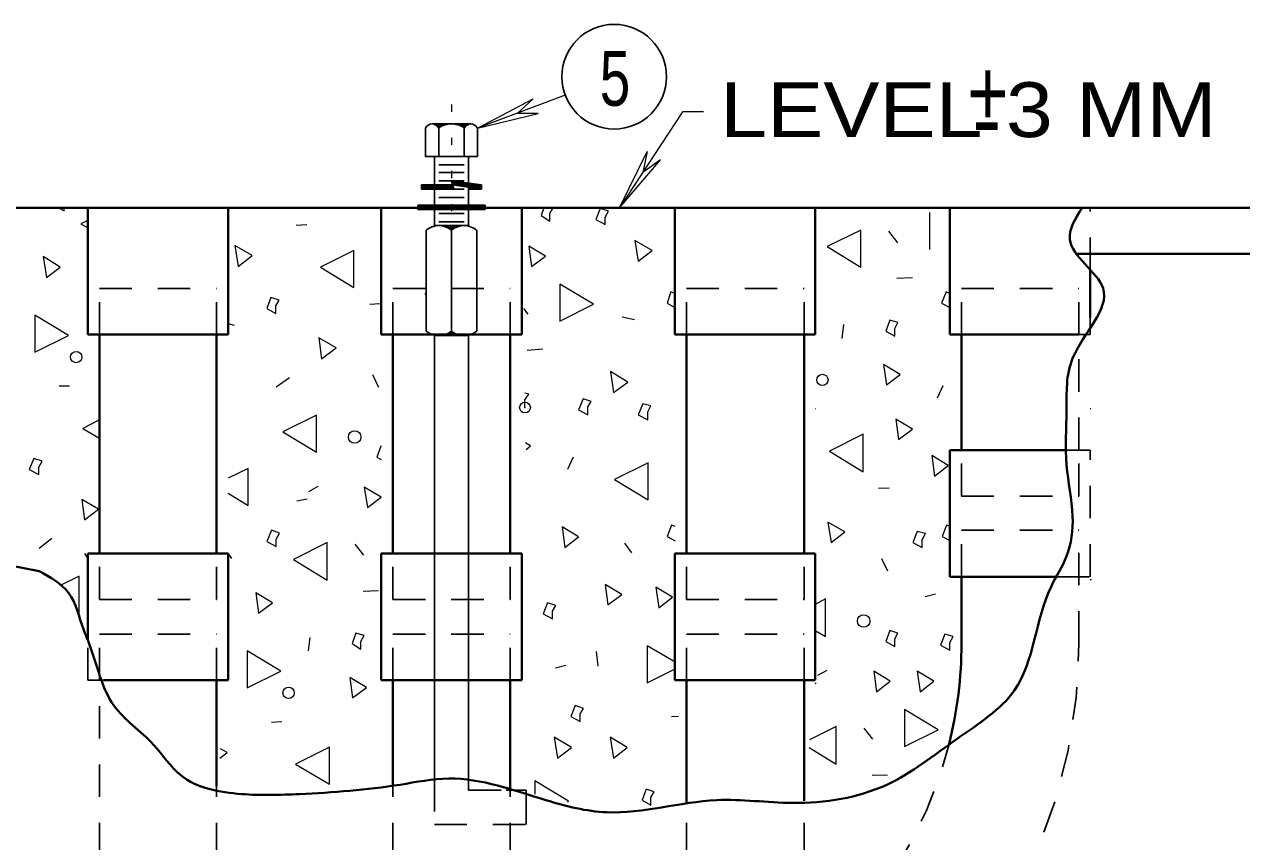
# Model space of a CAD drawing. Extents: x 312583 to 312854, y 144419 to 144597.
# Drawn here: x 312756.71 to 312773.6, y 144448.42 to 144459.75 of the extents above; entities that cross this region are included whole.
import ezdxf
from ezdxf.enums import TextEntityAlignment as Align

# ---------------------------------------------------------------- set-up
doc = ezdxf.new("R2010")
doc.units = 0
doc.header["$LTSCALE"] = 0.3
doc.header["$PDMODE"] = 32
doc.header["$PDSIZE"] = 0.15
doc.linetypes.add('DOTTED', pattern=[1.5, 0.3, -1.2])
doc.linetypes.add('SHORT_DASHED', pattern=[2.7, 1.5, -1.2])
for name, color, linetype, lineweight in [('1', 7, 'Continuous', 25), ('2', 7, 'Continuous', 13), ('52', 7, 'Continuous', 25)]:
    doc.layers.add(name, color=color, linetype=linetype, lineweight=lineweight)

msp = doc.modelspace()

# ---------------------------------------------------------------- linework, layer by layer
at = {"layer": '1', "lineweight": 40}
for p, q in [((312734.5276, 144457.2014), (312777.9746, 144457.2014)), ((312757.5966, 144455.4457), (312757.5966, 144457.2014)), ((312759.544, 144455.4457), (312759.544, 144457.2014)), ((312761.6676, 144455.4457), (312761.6676, 144457.2014)), ((312763.615, 144455.4457), (312763.615, 144457.2014)), ((312765.7386, 144455.4457), (312765.7386, 144457.2014)), ((312767.686, 144455.4457), (312767.686, 144457.2014)), ((312769.5566, 144455.4457), (312769.5566, 144457.2014)), ((312771.3123, 144456.565), (312784.1233, 144456.565)), ((312771.504, 144455.6834), (312771.504, 144456.3427)), ((312757.5966, 144455.4457), (312759.544, 144455.4457)), ((312757.7576, 144452.4097), (312757.7576, 144455.4457)), ((312759.383, 144452.4097), (312759.383, 144455.4457)), ((312761.6676, 144455.4457), (312763.615, 144455.4457)), ((312761.8286, 144452.4097), (312761.8286, 144455.4457)), ((312763.454, 144452.4097), (312763.454, 144455.4457)), ((312765.7386, 144455.4457), (312767.686, 144455.4457)), ((312765.8996, 144452.4097), (312765.8996, 144455.4457)), ((312767.5326, 144452.4097), (312767.5326, 144455.4457)), ((312769.5566, 144455.4457), (312771.343, 144455.4457)), ((312769.7176, 144453.8434), (312769.7176, 144455.4457)), ((312769.5566, 144452.0877), (312769.5566, 144453.8434)), ((312769.5566, 144453.8434), (312771.1743, 144453.8434)), ((312757.5966, 144452.4097), (312759.544, 144452.4097)), ((312757.5966, 144451.2137), (312757.5966, 144452.4097)), ((312759.544, 144450.654), (312759.544, 144452.4097)), ((312761.6676, 144450.654), (312761.6676, 144452.4097)), ((312761.6676, 144452.4097), (312763.615, 144452.4097)), ((312763.615, 144450.654), (312763.615, 144452.4097)), ((312765.7386, 144450.654), (312765.7386, 144452.4097)), ((312765.7386, 144452.4097), (312767.686, 144452.4097)), ((312767.686, 144450.654), (312767.686, 144452.4097)), ((312769.5566, 144452.0877), (312771.0363, 144452.0877)), ((312769.7176, 144451.16), (312769.7176, 144452.0877)), ((312757.819, 144450.654), (312759.544, 144450.654)), ((312759.383, 144449.182), (312759.383, 144450.654)), ((312761.6676, 144450.654), (312763.615, 144450.654)), ((312761.8286, 144449.1974), (312761.8286, 144450.654)), ((312763.454, 144449.113), (312763.454, 144450.654)), ((312765.7386, 144450.654), (312767.686, 144450.654)), ((312765.8996, 144448.9444), (312765.8996, 144450.654)), ((312767.5326, 144448.9827), (312767.5326, 144450.654))]:
    msp.add_line(p, q, dxfattribs=at)
at = {"layer": '1', "linetype": 'SHORT_DASHED'}
for p, q in [((312771.504, 144456.3427), (312771.504, 144457.2014)), ((312757.7576, 144456.082), (312759.383, 144456.082)), ((312757.7576, 144455.4457), (312757.7576, 144456.082)), ((312759.383, 144455.4457), (312759.383, 144456.082)), ((312761.8286, 144455.4457), (312761.8286, 144456.082)), ((312761.8286, 144456.082), (312763.454, 144456.082)), ((312763.454, 144455.4457), (312763.454, 144456.082)), ((312765.8996, 144456.082), (312767.5326, 144456.082)), ((312765.8996, 144455.4457), (312765.8996, 144456.082)), ((312767.5326, 144455.4457), (312767.5326, 144456.082)), ((312769.7176, 144456.082), (312771.343, 144456.082)), ((312769.7176, 144455.4457), (312769.7176, 144456.082)), ((312771.343, 144455.4457), (312771.343, 144456.082)), ((312771.504, 144455.4457), (312771.504, 144455.6834)), ((312771.343, 144453.8434), (312771.343, 144455.4457)), ((312771.343, 144455.4457), (312771.504, 144455.4457)), ((312769.7176, 144453.207), (312769.7176, 144453.8434)), ((312771.1743, 144453.8434), (312771.504, 144453.8434)), ((312771.343, 144453.207), (312771.343, 144453.8434)), ((312771.504, 144452.0877), (312771.504, 144453.8434)), ((312769.7176, 144453.207), (312771.343, 144453.207)), ((312769.7176, 144452.7317), (312771.343, 144452.7317)), ((312769.7176, 144452.0877), (312769.7176, 144452.7317)), ((312771.343, 144451.16), (312771.343, 144452.7317)), ((312757.7576, 144451.7734), (312757.7576, 144452.4097)), ((312759.383, 144451.7734), (312759.383, 144452.4097)), ((312761.8286, 144451.7734), (312761.8286, 144452.4097)), ((312763.454, 144451.7734), (312763.454, 144452.4097)), ((312765.8996, 144451.7734), (312765.8996, 144452.4097)), ((312767.5326, 144451.7734), (312767.5326, 144452.4097)), ((312771.0363, 144452.0877), (312771.504, 144452.0877)), ((312757.7576, 144451.7734), (312759.383, 144451.7734)), ((312761.8286, 144451.7734), (312763.454, 144451.7734)), ((312765.8996, 144451.7734), (312767.5326, 144451.7734)), ((312757.5966, 144450.654), (312757.5966, 144451.2137)), ((312757.7576, 144451.2904), (312759.383, 144451.2904)), ((312757.7576, 144450.654), (312757.7576, 144451.2904)), ((312759.383, 144450.654), (312759.383, 144451.2904)), ((312761.8286, 144450.654), (312761.8286, 144451.2904)), ((312761.8286, 144451.2904), (312763.454, 144451.2904)), ((312763.454, 144450.654), (312763.454, 144451.2904)), ((312765.8996, 144451.2904), (312767.5326, 144451.2904)), ((312765.8996, 144450.654), (312765.8996, 144451.2904)), ((312767.5326, 144450.654), (312767.5326, 144451.2904)), ((312757.5966, 144450.654), (312757.819, 144450.654)), ((312757.7576, 144439.315), (312757.7576, 144450.654)), ((312759.383, 144439.315), (312759.383, 144449.182)), ((312761.8286, 144439.315), (312761.8286, 144449.1974)), ((312763.454, 144439.315), (312763.454, 144449.113)), ((312767.5326, 144439.315), (312767.5326, 144448.9827)), ((312765.8996, 144439.315), (312765.8996, 144448.9444))]:
    msp.add_line(p, q, dxfattribs=at)
at = {"layer": '1', "lineweight": 13}
msp.add_line((312762.994, 144456.2584), (312763.0016, 144456.2507), dxfattribs=at)
at = {"layer": '1', "linetype": 'SHORT_DASHED'}
for radius, end in [(7.3792, 0), (5.75, 345.9494)]:
    msp.add_arc((312763.967, 144451.1639), radius, 270, end, dxfattribs=at)
at = {"layer": '1', "lineweight": 40}
msp.add_arc((312763.967, 144451.1639), 5.75, 345.9494, 0, dxfattribs=at)
for points in [[(312756.922, 144452.1644), (312757.3283, 144451.8654), (312757.5353, 144451.3594), (312757.6196, 144451.1447), (312757.957, 144450.3014), (312758.509, 144449.757), (312758.8846, 144449.3354), (312759.728, 144449.0747), (312760.533, 144449.0747), (312761.9283, 144449.205), (312762.603, 144449.2894), (312763.9523, 144448.9904), (312764.7956, 144448.8217), (312766.3213, 144448.9904), (312767.3716, 144448.952), (312768.6826, 144449.205), (312769.6563, 144449.8414), (312770.4536, 144450.516), (312770.9596, 144451.9497), (312771.1743, 144452.3714), (312771.2586, 144452.9234), (312771.1743, 144453.6364), (312771.1743, 144454.3954), (312771.2586, 144455.116), (312771.6803, 144456.0897), (312771.2203, 144456.7644), (312771.389, 144457.2014)], [(312756.922, 144452.1644), (312755.818, 144452.471), (312755.3273, 144452.724), (312753.8783, 144453.092), (312753.1806, 144453.4217), (312751.3023, 144453.8894)]]:
    msp.add_spline(points, degree=3, dxfattribs=at)
at = {"layer": '2'}
for p, q in [((312764.972, 144457.2014), (312765.3553, 144457.9834)), ((312765.3553, 144457.9834), (312765.294, 144457.692)), ((312764.972, 144457.2014), (312765.5393, 144457.8684)), ((312765.5393, 144457.8684), (312765.294, 144457.692)), ((312764.006, 144457.1247), (312764.052, 144457.2014)), ((312769.273, 144457.14), (312769.273, 144456.6264)), ((312760.487, 144456.9637), (312760.6326, 144456.9714)), ((312768.7056, 144456.8794), (312768.8283, 144456.7184)), ((312768.8206, 144456.2277), (312769.0353, 144456.2354)), ((312761.5066, 144455.8674), (312761.6523, 144455.875)), ((312763.638, 144455.806), (312763.6993, 144455.7294)), ((312759.544, 144455.599), (312759.6283, 144455.576)), ((312765.0103, 144455.691), (312765.179, 144455.6527)), ((312768.0616, 144455.392), (312768.0846, 144455.5837)), ((312763.6916, 144455.231), (312763.9063, 144455.2464)), ((312761.545, 144454.8937), (312761.6293, 144454.7174)), ((312757.198, 144454.7327), (312757.3436, 144454.7327)), ((312760.395, 144454.8477), (312760.211, 144454.7174)), ((312769.457, 144454.7327), (312769.3803, 144454.564)), ((312763.661, 144454.4337), (312763.661, 144454.541)), ((312767.686, 144454.4184), (312767.6936, 144454.4184)), ((312771.504, 144454.4184), (312771.5116, 144454.4184)), ((312764.328, 144453.7437), (312764.2513, 144453.575)), ((312759.544, 144453.2454), (312759.82, 144453.0767)), ((312760.6633, 144453.2684), (312760.7936, 144453.345)), ((312768.5676, 144453.3144), (312768.7133, 144453.322)), ((312760.4946, 144453.138), (312760.6403, 144453.1687)), ((312757.0983, 144452.6167), (312756.922, 144452.4787)), ((312761.2996, 144452.54), (312761.4223, 144452.3867)), ((312765.041, 144452.5554), (312765.1406, 144452.4174)), ((312757.5506, 144452.4097), (312757.5966, 144452.3407)), ((312759.544, 144452.4097), (312759.59, 144452.3407)), ((312768.606, 144452.3407), (312768.6903, 144452.172)), ((312771.504, 144452.0494), (312771.5193, 144452.0494)), ((312761.4146, 144451.8884), (312761.6293, 144451.896)), ((312769.2116, 144451.8117), (312769.3573, 144451.85)), ((312767.686, 144451.344), (312767.8316, 144451.2597)), ((312760.6556, 144451.0604), (312760.6786, 144451.2444)), ((312764.65, 144451.0527), (312764.673, 144450.8457)), ((312765.754, 144450.8994), (312765.3553, 144451.1294)), ((312764.0826, 144450.8227), (312764.2283, 144450.861)), ((312767.7243, 144450.723), (312767.8546, 144450.792)), ((312767.686, 144450.608), (312767.7013, 144450.6157)), ((312765.6926, 144450.148), (312765.7923, 144450.1557)), ((312760.142, 144450.0714), (312760.2876, 144450.079)), ((312768.3606, 144449.987), (312768.4833, 144449.8337)), ((312767.6016, 144449.7187), (312767.9773, 144449.4887)), ((312768.4756, 144449.3354), (312768.6903, 144449.343)), ((312763.799, 144449.2587), (312763.799, 144449.0747))]:
    msp.add_line(p, q, dxfattribs=at)
for points in [[(312766.1373, 144458.5354), (312765.846, 144458.5354), (312764.972, 144457.2014)], [(312757.1903, 144457.2014), (312757.267, 144457.163), (312757.267, 144457.2014)], [(312763.9216, 144457.2014), (312763.8833, 144457.094), (312764.006, 144457.0174), (312764.006, 144457.1247)], [(312757.5966, 144457.025), (312757.497, 144456.979), (312757.5966, 144456.9254)], [(312765.7386, 144456.013), (312765.685, 144456.036), (312765.6313, 144455.8827), (312765.7386, 144455.8214)], [(312769.5566, 144456.013), (312769.503, 144456.036), (312769.4416, 144455.8827), (312769.5566, 144455.8214)], [(312763.661, 144454.541), (312763.7146, 144454.6177), (312763.661, 144454.633)], [(312757.75, 144454.2574), (312757.5276, 144454.1424), (312757.75, 144454.012)], [(312761.6676, 144453.897), (312761.66, 144453.897), (312761.6063, 144453.7437), (312761.6676, 144453.713)], [(312763.6763, 144453.851), (312763.7376, 144453.9047), (312763.6686, 144453.943)], [(312759.82, 144453.0767), (312759.82, 144453.5904), (312759.544, 144453.4524)], [(312765.7463, 144452.7854), (312765.6926, 144452.8007), (312765.6313, 144452.6474), (312765.7463, 144452.586)], [(312769.5643, 144452.7854), (312769.5106, 144452.8007), (312769.4493, 144452.6474), (312769.5643, 144452.586)], [(312757.474, 144451.5817), (312757.474, 144452.0954), (312757.2133, 144451.965)], [(312767.8316, 144451.2597), (312767.8316, 144451.781), (312767.686, 144451.7044)], [(312765.3553, 144451.1294), (312765.3553, 144450.6157), (312765.754, 144450.815)], [(312767.9773, 144449.4887), (312767.9773, 144450.01), (312767.6093, 144449.826)], [(312759.429, 144449.573), (312759.5286, 144449.6497), (312759.4366, 144449.7034)], [(312764.2513, 144448.9674), (312764.2666, 144448.975), (312763.799, 144449.2587)]]:
    msp.add_lwpolyline(points, dxfattribs=at)
for points in [[(312764.7726, 144457.071), (312764.8186, 144457.1554), (312764.7036, 144457.1937), (312764.6423, 144457.0404), (312764.7726, 144456.9714)], [(312765.2326, 144456.4654), (312765.4243, 144456.611), (312765.1866, 144456.749)], [(312768.3223, 144456.381), (312768.3223, 144456.8947), (312767.8546, 144456.6647)], [(312759.682, 144456.3887), (312759.8736, 144456.542), (312759.636, 144456.68)], [(312761.2843, 144456.0974), (312761.2843, 144456.611), (312760.8243, 144456.381)], [(312763.753, 144456.3887), (312763.9446, 144456.5344), (312763.7146, 144456.6724)], [(312757.0216, 144456.2354), (312757.2133, 144456.381), (312756.9756, 144456.5267)], [(312764.144, 144456.1434), (312764.144, 144455.6297), (312764.6116, 144455.8674)], [(312760.2033, 144455.8444), (312760.2493, 144455.921), (312760.1343, 144455.9594), (312760.0806, 144455.806), (312760.2033, 144455.737)], [(312756.8606, 144455.714), (312756.8606, 144455.2004), (312757.3283, 144455.4304)], [(312768.79, 144455.53), (312768.836, 144455.6144), (312768.721, 144455.645), (312768.6673, 144455.4917), (312768.79, 144455.4227)], [(312760.8396, 144455.1084), (312761.039, 144455.2617), (312760.8013, 144455.3997)], [(312764.8876, 144454.6407), (312765.087, 144454.7864), (312764.8493, 144454.932)], [(312768.675, 144454.748), (312768.8666, 144454.8937), (312768.6366, 144455.0317)], [(312764.535, 144454.4414), (312764.581, 144454.518), (312764.466, 144454.5564), (312764.4046, 144454.403), (312764.535, 144454.334)], [(312765.363, 144454.3724), (312765.409, 144454.4567), (312765.294, 144454.4874), (312765.2326, 144454.334), (312765.363, 144454.265)], [(312760.7706, 144453.8127), (312760.7706, 144454.3264), (312760.303, 144454.0964)], [(312768.8436, 144453.989), (312769.0353, 144454.1347), (312768.8053, 144454.2727)], [(312768.353, 144453.5444), (312768.353, 144454.0657), (312767.8853, 144453.828)], [(312756.9143, 144453.6057), (312756.9603, 144453.69), (312756.8453, 144453.7284), (312756.784, 144453.575), (312756.9143, 144453.506)], [(312769.342, 144453.483), (312769.5336, 144453.6287), (312769.3036, 144453.7667)], [(312765.3706, 144453.1534), (312765.3706, 144453.667), (312764.903, 144453.437)], [(312761.476, 144453.046), (312761.6676, 144453.1917), (312761.43, 144453.3297)], [(312757.5506, 144452.8774), (312757.7423, 144453.023), (312757.5123, 144453.161)], [(312767.9083, 144452.563), (312768.1, 144452.7087), (312767.8623, 144452.8467)], [(312760.211, 144452.609), (312760.257, 144452.6934), (312760.142, 144452.7317), (312760.0806, 144452.5784), (312760.211, 144452.5094)], [(312764.213, 144452.494), (312764.4046, 144452.6397), (312764.1746, 144452.7777)], [(312769.1733, 144452.6014), (312769.2193, 144452.6857), (312769.1043, 144452.7164), (312769.043, 144452.563), (312769.1733, 144452.494)], [(312760.9163, 144452.0417), (312760.9163, 144452.563), (312760.4486, 144452.3254)], [(312759.9656, 144451.5817), (312760.1573, 144451.7274), (312759.9273, 144451.8654)], [(312764.811, 144451.6967), (312765.0026, 144451.8424), (312764.7726, 144451.9804)], [(312765.5163, 144451.6584), (312765.708, 144451.804), (312765.478, 144451.942)], [(312764.0443, 144451.6124), (312764.0903, 144451.689), (312763.9753, 144451.7274), (312763.914, 144451.574), (312764.0443, 144451.505)], [(312768.79, 144451.229), (312768.836, 144451.3057), (312768.721, 144451.344), (312768.6673, 144451.1907), (312768.79, 144451.1217)], [(312761.384, 144451.1907), (312761.43, 144451.275), (312761.315, 144451.3057), (312761.2613, 144451.16), (312761.384, 144451.0834)], [(312769.5566, 144451.1754), (312769.6026, 144451.2597), (312769.4876, 144451.2904), (312769.4263, 144451.137), (312769.5566, 144451.068)], [(312759.8046, 144451.0604), (312759.8046, 144450.5467), (312760.2723, 144450.7767)], [(312761.269, 144450.4087), (312761.4606, 144450.5544), (312761.2306, 144450.6924)], [(312768.537, 144450.493), (312768.7286, 144450.6387), (312768.4986, 144450.7767)], [(312769.1426, 144450.493), (312769.3343, 144450.6387), (312769.1043, 144450.7767)], [(312764.4276, 144450.1864), (312764.4736, 144450.263), (312764.3586, 144450.3014), (312764.2973, 144450.148), (312764.4276, 144450.079)], [(312768.928, 144450.2477), (312768.928, 144449.734), (312769.3956, 144449.964)], [(312764.1133, 144449.573), (312764.305, 144449.7187), (312764.0673, 144449.8644)], [(312764.8876, 144449.573), (312765.0793, 144449.7187), (312764.8416, 144449.8644)], [(312760.947, 144449.2127), (312760.947, 144449.7264), (312760.4793, 144449.4887)], [(312765.409, 144449.0287), (312765.455, 144449.1054), (312765.34, 144449.1437), (312765.2863, 144448.9904), (312765.409, 144448.9214)]]:
    msp.add_lwpolyline(points, close=True, dxfattribs=at)
for centre, radius in [((312757.4345, 144455.1336), 0.0784), ((312767.7875, 144454.8162), 0.0784), ((312761.2989, 144454.0251), 0.0865), ((312768.3603, 144451.4732), 0.0865), ((312760.3814, 144450.4783), 0.0784)]:
    msp.add_circle(centre, radius, dxfattribs=at)
msp.add_point((312763.661, 144454.4337), dxfattribs=at)
at = {"layer": '52', "lineweight": 13}
for p, q in [((312764.2206, 144458.7654), (312763.0016, 144458.3054)), ((312763.0016, 144458.3054), (312763.776, 144458.7117)), ((312763.776, 144458.7117), (312763.5536, 144458.5124)), ((312763.0016, 144458.3054), (312763.845, 144458.5124)), ((312763.845, 144458.5124), (312763.5536, 144458.5124))]:
    msp.add_line(p, q, dxfattribs=at)
at = {"layer": '52', "linetype": 'DOTTED', "lineweight": 13}
msp.add_line((312762.6413, 144458.635), (312762.6413, 144456.956), dxfattribs=at)
at = {"layer": '52'}
for p, q in [((312762.281, 144458.3054), (312762.281, 144457.9144)), ((312762.9096, 144458.3667), (312762.373, 144458.3667)), ((312762.465, 144458.3054), (312762.465, 144457.9144)), ((312762.8176, 144458.3054), (312762.8176, 144457.9144)), ((312763.0016, 144458.3054), (312763.0016, 144457.9144)), ((312763.0016, 144457.9144), (312762.281, 144457.9144)), ((312762.4036, 144457.9144), (312762.4036, 144456.956)), ((312762.879, 144457.9144), (312762.879, 144456.956)), ((312762.8176, 144457.7994), (312762.465, 144457.7994)), ((312762.8176, 144457.692), (312762.465, 144457.692)), ((312762.8176, 144457.577), (312762.465, 144457.577)), ((312762.2273, 144457.5234), (312762.2273, 144457.462)), ((312762.6566, 144457.5234), (312762.2273, 144457.5234)), ((312762.672, 144457.462), (312762.2273, 144457.462)), ((312762.8176, 144457.462), (312762.465, 144457.462)), ((312763.0553, 144457.5234), (312763.0553, 144457.462)), ((312763.109, 144457.2397), (312762.1736, 144457.2397)), ((312762.1736, 144457.2397), (312762.1736, 144457.1784)), ((312762.8176, 144457.347), (312762.465, 144457.347)), ((312763.109, 144457.2397), (312763.109, 144457.1784)), ((312763.109, 144457.2244), (312762.1736, 144457.2244)), ((312763.109, 144457.209), (312762.1736, 144457.209)), ((312763.109, 144457.1937), (312762.1736, 144457.1937)), ((312763.109, 144457.1784), (312762.1736, 144457.1784)), ((312762.8176, 144457.1247), (312762.465, 144457.1247)), ((312762.879, 144456.956), (312762.4036, 144456.956)), ((312762.8176, 144457.0097), (312762.465, 144457.0097)), ((312762.8176, 144456.956), (312762.465, 144456.956)), ((312762.6413, 144456.956), (312762.6413, 144455.4304)), ((312762.2886, 144456.8947), (312762.2886, 144455.4917)), ((312762.994, 144456.8947), (312762.994, 144455.4917)), ((312762.2886, 144456.013), (312762.2733, 144456.0054)), ((312762.4036, 144455.4304), (312762.4036, 144449.2817)), ((312762.8176, 144455.4304), (312762.465, 144455.4304)), ((312762.879, 144455.4304), (312762.879, 144449.251))]:
    msp.add_line(p, q, dxfattribs=at)
at = {"layer": '52', "linetype": 'SHORT_DASHED'}
for p, q in [((312762.4036, 144449.2817), (312762.4036, 144448.653)), ((312762.879, 144449.251), (312762.879, 144449.1284)), ((312762.879, 144449.1284), (312763.4003, 144449.1284)), ((312763.6763, 144449.0594), (312763.6763, 144448.653)), ((312762.4036, 144448.653), (312763.6763, 144448.653))]:
    msp.add_line(p, q, dxfattribs=at)
at = {"layer": '52'}
for points in [[(312762.396, 144458.3667), (312762.5953, 144458.3667), (312762.5646, 144458.359), (312762.5416, 144458.3514), (312762.5033, 144458.336), (312762.465, 144458.313), (312762.4496, 144458.336), (312762.4343, 144458.3437), (312762.4036, 144458.359), (312762.58, 144458.359), (312762.5263, 144458.3514), (312762.4956, 144458.336), (312762.465, 144458.3207), (312762.4343, 144458.3437), (312762.419, 144458.359), (312762.557, 144458.359), (312762.511, 144458.3437), (312762.465, 144458.3207), (312762.4266, 144458.359), (312762.5416, 144458.359), (312762.465, 144458.3284), (312762.4343, 144458.3514), (312762.5263, 144458.359), (312762.4573, 144458.3284), (312762.442, 144458.3514), (312762.511, 144458.3514), (312762.465, 144458.336), (312762.4496, 144458.3514), (312762.4956, 144458.3514), (312762.465, 144458.336), (312762.4573, 144458.3514), (312762.4803, 144458.3437), (312762.465, 144458.3437)], [(312762.8866, 144458.3667), (312762.6873, 144458.3667), (312762.718, 144458.359), (312762.741, 144458.3514), (312762.7793, 144458.336), (312762.8176, 144458.313), (312762.833, 144458.336), (312762.8483, 144458.3437), (312762.879, 144458.359), (312762.7026, 144458.359), (312762.7563, 144458.3514), (312762.787, 144458.336), (312762.8176, 144458.3207), (312762.8483, 144458.3437), (312762.8636, 144458.359), (312762.7256, 144458.359), (312762.7716, 144458.3437), (312762.8176, 144458.3207), (312762.856, 144458.359), (312762.741, 144458.359), (312762.8176, 144458.3284), (312762.8483, 144458.3514), (312762.7563, 144458.359), (312762.8176, 144458.3284), (312762.8406, 144458.3514), (312762.7716, 144458.3514), (312762.8176, 144458.336), (312762.833, 144458.3514), (312762.787, 144458.3514), (312762.8176, 144458.336), (312762.8253, 144458.3514), (312762.8023, 144458.3437), (312762.8176, 144458.3437)], [(312763.0553, 144457.5234), (312762.6413, 144457.577), (312762.672, 144457.462)], [(312762.6643, 144457.4697), (312762.235, 144457.4697), (312762.235, 144457.5157), (312762.649, 144457.508), (312762.6643, 144457.4774), (312762.2426, 144457.4774), (312762.2426, 144457.508), (312762.649, 144457.5004), (312762.6566, 144457.485), (312762.2503, 144457.485), (312762.258, 144457.4927), (312762.258, 144457.5004), (312762.6413, 144457.5004), (312762.649, 144457.4927), (312762.258, 144457.4927)], [(312762.879, 144457.462), (312763.0553, 144457.4697), (312763.0476, 144457.5157), (312762.649, 144457.5694), (312762.6643, 144457.5234), (312762.879, 144457.4927), (312762.8866, 144457.4697), (312763.0476, 144457.4774), (312763.04, 144457.508), (312762.6643, 144457.5617), (312762.672, 144457.531), (312762.8943, 144457.4927), (312762.8943, 144457.4774), (312763.04, 144457.485), (312763.04, 144457.5004), (312762.6796, 144457.554), (312762.6796, 144457.5387), (312762.8866, 144457.5004), (312762.902, 144457.4927), (312762.948, 144457.485), (312763.0323, 144457.4927), (312762.6873, 144457.5464), (312762.9786, 144457.4927)], [(312762.6566, 144457.5234), (312763.0553, 144457.462), (312762.879, 144457.462)], [(312762.7716, 144456.956), (312762.511, 144456.956), (312762.5416, 144456.9484), (312762.5646, 144456.9407), (312762.5953, 144456.9254), (312762.6183, 144456.9177), (312762.6413, 144456.9024), (312762.6413, 144456.8947), (312762.6873, 144456.9254), (312762.7333, 144456.9484), (312762.7563, 144456.9484), (312762.5263, 144456.956), (312762.5493, 144456.9484), (312762.5646, 144456.9484), (312762.5953, 144456.933), (312762.626, 144456.9177), (312762.6336, 144456.91), (312762.6413, 144456.9024), (312762.6873, 144456.933), (312762.7333, 144456.9484), (312762.5646, 144456.9484), (312762.603, 144456.933), (312762.6413, 144456.91), (312762.718, 144456.9484), (312762.58, 144456.9484), (312762.6413, 144456.91), (312762.7026, 144456.9407), (312762.5953, 144456.9484), (312762.6413, 144456.9177), (312762.6796, 144456.9407), (312762.6106, 144456.9407), (312762.6413, 144456.933), (312762.6796, 144456.933), (312762.6566, 144456.9254), (312762.649, 144456.9407), (312762.6413, 144456.9177), (312762.626, 144456.933), (312762.6183, 144456.933), (312762.603, 144456.9407)], [(312762.7716, 144455.4304), (312762.511, 144455.4304), (312762.5416, 144455.438), (312762.5646, 144455.4457), (312762.5953, 144455.4534), (312762.6183, 144455.4687), (312762.6413, 144455.484), (312762.6413, 144455.484), (312762.6873, 144455.4534), (312762.7333, 144455.438), (312762.7563, 144455.4304), (312762.5263, 144455.4304), (312762.5493, 144455.438), (312762.5646, 144455.438), (312762.5953, 144455.4457), (312762.626, 144455.461), (312762.6336, 144455.4764), (312762.6413, 144455.484), (312762.6873, 144455.4534), (312762.7333, 144455.438), (312762.5646, 144455.438), (312762.603, 144455.4457), (312762.6413, 144455.4764), (312762.718, 144455.438), (312762.58, 144455.438), (312762.6413, 144455.4764), (312762.7026, 144455.438), (312762.5953, 144455.438), (312762.6413, 144455.4687), (312762.6796, 144455.4457), (312762.6106, 144455.4457), (312762.6413, 144455.4534), (312762.6796, 144455.4457), (312762.6566, 144455.461), (312762.649, 144455.4457), (312762.6413, 144455.4687), (312762.626, 144455.4534), (312762.6183, 144455.4534), (312762.603, 144455.4457)], [(312763.4003, 144449.1284), (312763.6763, 144449.1284), (312763.6763, 144449.0594)]]:
    msp.add_lwpolyline(points, dxfattribs=at)
msp.add_circle((312764.8985, 144459.0209), 0.7254, dxfattribs=at)
for centre, radius, start, end in [((312762.372, 144458.2665), 0.0993, 25.60064, 154.39936), ((312762.6407, 144458.0531), 0.3126, 55.04559, 124.95441), ((312762.9093, 144458.2665), 0.0993, 25.60064, 154.39936), ((312762.4659, 144456.6839), 0.272, 50.00693, 129.99306), ((312762.8155, 144456.6839), 0.272, 50.00694, 129.99307), ((312762.4659, 144455.7013), 0.272, 230.00694, 309.99307), ((312762.8155, 144455.7013), 0.272, 230.00693, 309.99306)]:
    msp.add_arc(centre, radius, start, end, dxfattribs=at)

# ---------------------------------------------------------------- texts
at = {"layer": '2', "width": 0.8}
msp.add_text('+', height=0.92, rotation=180, dxfattribs=at).set_placement((312770.0833, 144459.2275), align=Align.CENTER)
at = {"layer": '2', "width": 1.15}
msp.add_text('LEVEL 3 MM', height=0.76, dxfattribs=at).set_placement((312766.3699, 144458.1834))
at = {"layer": '2'}
msp.add_text('-', height=0.92, rotation=180, dxfattribs=at).set_placement((312770.0676, 144458.689), align=Align.CENTER)
at = {"layer": '52', "width": 0.75}
msp.add_text('5', height=0.76, dxfattribs=at).set_placement((312764.6978, 144458.6179))

doc.saveas('drawing.dxf')
